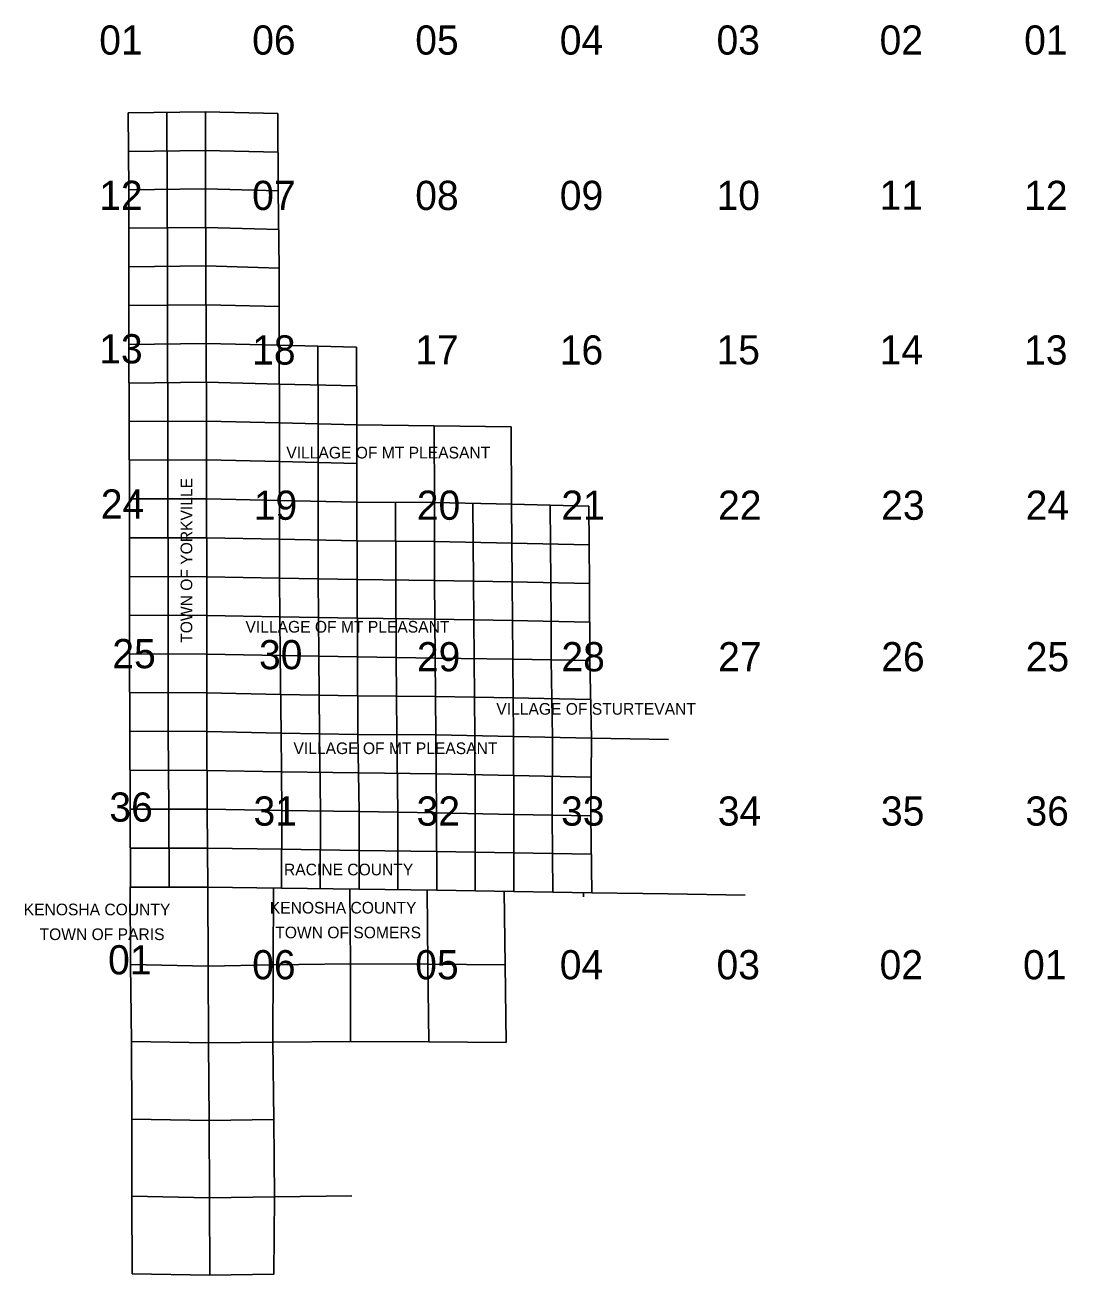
# Model space of a CAD drawing. Extents: x 587895 to 623621, y 151776 to 194601.
import ezdxf

# ---------------------------------------------------------------- set-up
doc = ezdxf.new("R2010")
doc.units = 0
for name, color, linetype in [('E_ALI', 7, 'Continuous'), ('E_ALI_CPI', 7, 'Continuous'), ('E_ALI_Equation', 7, 'Continuous'), ('E_ALI_Sta', 7, 'Continuous')]:
    doc.layers.add(name, color=color, linetype=linetype)

msp = doc.modelspace()

# ---------------------------------------------------------------- linework, layer by layer
at = {"layer": 'E_ALI'}
for p, q in [((591430, 191595), (594075, 191625)), ((594081, 188985), (594075, 191625)), ((594075, 191625), (596550, 191569)), ((594081, 188985), (594091, 186347)), ((591452, 186321), (594091, 186347)), ((594091, 186347), (594100, 183686)), ((594091, 186347), (596599, 186276)), ((594100, 183686), (594107, 181033)), ((599250, 183567), (599256, 180908)), ((594107, 181033), (591459, 181013)), ((594107, 181033), (594113, 178369)), ((596609, 180972), (594107, 181033)), ((599256, 180908), (596609, 180972)), ((599256, 180908), (599265, 178254)), ((599256, 180908), (601913, 180868)), ((601913, 180868), (604543, 180829)), ((604563, 178181), (604543, 180829)), ((594113, 178369), (594118, 175696)), ((599265, 178254), (599268, 175602)), ((604582, 175527), (604563, 178181)), ((591479, 175702), (594118, 175696)), ((594118, 175696), (594121, 173044)), ((594118, 175696), (596616, 175650)), ((596616, 175650), (599268, 175602)), ((599268, 175602), (599282, 172950)), ((599268, 175602), (601923, 175567)), ((601923, 175567), (604582, 175527)), ((604606, 172875), (604582, 175527)), ((604582, 175527), (607227, 175467)), ((594121, 173044), (594127, 170399)), ((599282, 172950), (599296, 170298)), ((604629, 170230), (604606, 172875)), ((591482, 170411), (594127, 170399)), ((594127, 170399), (594140, 167731)), ((594127, 170399), (596664, 170342)), ((596664, 170342), (599296, 170298)), ((599296, 170298), (599341, 167652)), ((599296, 170298), (601971, 170278)), ((601971, 170278), (604629, 170230)), ((604634, 167558), (604629, 170230)), ((604629, 170230), (607296, 170165)), ((607296, 170165), (609932, 170123)), ((594140, 167731), (594155, 165067)), ((599341, 167652), (599341, 164996)), ((604638, 164918), (604634, 167558)), ((591509, 165066), (594155, 165067)), ((594155, 165067), (596682, 165030)), ((594155, 165067), (594166, 162359)), ((596682, 165030), (599341, 164996)), ((599018, 165000), (599030, 163717)), ((599341, 164996), (601999, 164961)), ((601999, 164961), (604638, 164918)), ((604344, 162398), (604307, 164924)), ((604638, 164918), (607310, 164873)), ((607310, 164873), (609922, 164836)), ((609922, 164836), (612561, 164789)), ((599030, 163717), (599041, 162434)), ((594166, 162359), (594182, 159728)), ((599041, 162434), (599050, 159776)), ((604344, 162398), (604378, 159745)), ((591540, 159773), (594182, 159728)), ((594182, 159728), (596389, 159755)), ((596389, 159755), (599050, 159776)), ((599050, 159776), (601722, 159764)), ((601722, 159764), (604378, 159745)), ((594182, 159728), (594199, 157074)), ((594199, 157074), (594209, 154424)), ((591556, 154474), (594209, 154424)), ((594209, 154424), (596440, 154452)), ((594209, 154424), (594227, 151776)), ((596440, 154452), (599095, 154484))]:
    msp.add_line(p, q, dxfattribs=at)
at = {"layer": 'E_ALI_Equation'}
for p, q in [((591430, 191595), (591446, 188952)), ((596550, 191569), (596568, 188923)), ((594081, 188985), (591446, 188952)), ((591446, 188952), (591452, 186321)), ((594081, 188985), (596568, 188923)), ((596568, 188923), (596599, 186276)), ((591452, 186321), (591456, 183659)), ((596599, 186276), (596604, 183628)), ((591456, 183659), (594100, 183686)), ((591456, 183659), (591459, 181013)), ((594100, 183686), (596604, 183628)), ((596604, 183628), (596609, 180972)), ((596604, 183628), (599250, 183567)), ((591459, 181013), (591473, 178363)), ((596609, 180972), (596612, 178313)), ((601916, 178237), (601913, 180868)), ((591473, 178363), (594113, 178369)), ((591473, 178363), (591479, 175702)), ((594113, 178369), (596612, 178313)), ((596612, 178313), (596616, 175650)), ((596612, 178313), (599265, 178254)), ((599265, 178254), (601916, 178237)), ((601923, 175567), (601916, 178237)), ((601916, 178237), (604563, 178181)), ((604563, 178181), (607213, 178117)), ((607213, 178117), (607227, 175467)), ((591479, 175702), (591480, 173056)), ((596616, 175650), (596640, 172998)), ((601947, 172913), (601923, 175567)), ((607227, 175467), (607241, 172825)), ((591480, 173056), (591482, 170411)), ((594121, 173044), (591480, 173056)), ((596640, 172998), (594121, 173044)), ((596640, 172998), (596664, 170342)), ((599282, 172950), (596640, 172998)), ((601947, 172913), (599282, 172950)), ((601971, 170278), (601947, 172913)), ((604606, 172875), (601947, 172913)), ((607241, 172825), (604606, 172875)), ((607241, 172825), (607296, 170165)), ((591482, 170411), (591499, 167739)), ((596664, 170342), (596692, 167690)), ((601985, 167605), (601971, 170278)), ((607296, 170165), (607276, 167509)), ((591499, 167739), (591509, 165066)), ((591499, 167739), (594140, 167731)), ((594140, 167731), (596692, 167690)), ((596692, 167690), (596682, 165030)), ((596692, 167690), (599341, 167652)), ((599341, 167652), (601985, 167605)), ((601999, 164961), (601985, 167605)), ((601985, 167605), (604634, 167558)), ((604634, 167558), (607276, 167509)), ((607276, 167509), (607310, 164873)), ((591492, 165066), (591512, 162418)), ((596405, 165034), (596397, 162401)), ((601696, 162428), (601672, 164965)), ((607023, 164737), (607025, 164877)), ((591512, 162418), (591540, 159773)), ((591512, 162418), (594166, 162359)), ((594166, 162359), (596397, 162401)), ((596397, 162401), (596389, 159755)), ((596397, 162401), (599041, 162434)), ((599041, 162434), (601696, 162428)), ((601722, 159764), (601696, 162428)), ((601696, 162428), (604344, 162398)), ((591540, 159773), (591550, 157118)), ((596389, 159755), (596416, 157103)), ((591550, 157118), (591556, 154474)), ((591550, 157118), (594199, 157074)), ((594199, 157074), (596416, 157103)), ((596416, 157103), (596440, 154452)), ((591556, 154474), (591565, 151819)), ((596440, 154452), (596414, 151805)), ((591565, 151819), (594227, 151776)), ((594227, 151776), (596414, 151805))]:
    msp.add_line(p, q, dxfattribs=at)
at = {"layer": 'E_ALI_Sta'}
for p, q in [((592752, 191610), (592763, 188969)), ((591438, 190273), (594078, 190305)), ((594078, 190305), (596559, 190246)), ((592763, 188969), (592771, 186334)), ((594086, 187666), (591449, 187637)), ((596584, 187600), (594086, 187666)), ((592771, 186334), (592778, 183672)), ((591454, 184990), (594095, 185017)), ((594095, 185017), (596602, 184952)), ((592778, 183672), (592783, 181023)), ((597933, 180940), (597927, 183597)), ((594104, 182360), (591457, 182336)), ((596607, 182300), (594104, 182360)), ((599253, 182237), (596607, 182300)), ((592783, 181023), (592793, 178366)), ((597938, 178283), (597933, 180940)), ((591466, 179688), (594110, 179701)), ((594110, 179701), (596611, 179643)), ((596611, 179643), (599260, 179581)), ((592793, 178366), (592798, 175699)), ((597942, 175626), (597938, 178283)), ((600590, 178245), (600595, 175585)), ((603252, 175547), (603239, 178209)), ((605888, 178149), (605905, 175497)), ((594115, 177032), (591476, 177033)), ((596614, 176982), (594115, 177032)), ((599266, 176928), (596614, 176982)), ((601919, 176902), (599266, 176928)), ((604572, 176854), (601919, 176902)), ((607220, 176792), (604572, 176854)), ((592798, 175699), (592801, 173050)), ((597961, 172974), (597942, 175626)), ((600595, 175585), (600614, 172931)), ((603277, 172894), (603252, 175547)), ((605905, 175497), (605914, 174174)), ((591480, 174379), (594119, 174370)), ((594119, 174370), (596628, 174324)), ((596628, 174324), (599275, 174276)), ((599275, 174276), (601935, 174240)), ((601935, 174240), (604594, 174201)), ((604594, 174201), (607234, 174146)), ((605914, 174174), (605923, 172850)), ((592801, 173050), (592804, 170405)), ((597980, 170320), (597961, 172974)), ((600614, 172931), (600633, 170288)), ((603300, 170254), (603277, 172894)), ((605923, 172850), (605962, 170197)), ((594124, 171722), (591481, 171734)), ((596652, 171670), (594124, 171722)), ((599289, 171624), (596652, 171670)), ((601959, 171595), (599289, 171624)), ((601959, 171595), (604618, 171553)), ((604618, 171553), (607268, 171495)), ((592804, 170405), (592820, 167735)), ((598017, 167671), (597980, 170320)), ((600633, 170288), (600663, 167628)), ((603309, 167581), (603300, 170254)), ((605962, 170197), (605955, 167534)), ((591490, 169075), (594134, 169065)), ((594134, 169065), (596678, 169016)), ((596678, 169016), (599318, 168975)), ((599318, 168975), (601978, 168941)), ((601978, 168941), (604631, 168894)), ((604631, 168894), (607286, 168837)), ((592820, 167735), (592832, 165067)), ((598011, 165013), (598017, 167671)), ((600663, 167628), (600670, 164978)), ((603319, 164940), (603309, 167581)), ((605955, 167534), (605974, 164895)), ((594148, 166399), (591504, 166403)), ((596687, 166360), (594148, 166399)), ((599341, 166324), (596687, 166360)), ((601992, 166283), (599341, 166324)), ((604636, 166238), (601992, 166283)), ((607293, 166191), (604636, 166238))]:
    msp.add_line(p, q, dxfattribs=at)

# ---------------------------------------------------------------- texts
msp.add_text('Corner Missing', height=12).set_placement((606846, 164848))
at = {"layer": 'E_ALI_CPI'}
for s, height, p in [('01', 1000, (590438, 193587)), ('06', 1000, (595676, 193587)), ('05', 1000, (601262, 193587)), ('04', 1000, (606213, 193587)), ('03', 1000, (611582, 193587)), ('02', 1000, (617167, 193587)), ('01', 1000, (622118, 193587)), ('12', 1000, (590438, 188264)), ('07', 1000, (595676, 188264)), ('08', 1000, (601262, 188264)), ('09', 1000, (606213, 188264)), ('10', 1000, (611582, 188264)), ('11', 1000, (617167, 188271)), ('12', 1000, (622118, 188264)), ('13', 1000, (590438, 183009)), ('18', 1000, (595676, 182968)), ('17', 1000, (601262, 182975)), ('16', 1000, (606213, 182969)), ('15', 1000, (611582, 182975)), ('14', 1000, (617167, 182975)), ('13', 1000, (622118, 182968)), ('VILLAGE OF MT PLEASANT', 400, (596846, 179751)), ('24', 1000, (590492, 177690)), ('19', 1000, (595731, 177650)), ('20', 1000, (601317, 177650)), ('21', 1000, (606267, 177650)), ('22', 1000, (611636, 177650)), ('23', 1000, (617222, 177650)), ('24', 1000, (622172, 177650)), ('VILLAGE OF MT PLEASANT', 400, (595447, 173785)), ('25', 1000, (590885, 172565)), ('30', 1000, (595911, 172529)), ('29', 1000, (601319, 172459)), ('28', 1000, (606269, 172459)), ('27', 1000, (611638, 172459)), ('26', 1000, (617224, 172459)), ('25', 1000, (622174, 172459)), ('VILLAGE OF STURTEVANT', 400, (604039, 170972)), ('VILLAGE OF MT PLEASANT', 400, (597091, 169622)), ('36', 1000, (590785, 167309)), ('31', 1000, (595723, 167172)), ('32', 1000, (601309, 167172)), ('33', 1000, (606259, 167172)), ('34', 1000, (611628, 167172)), ('35', 1000, (617214, 167172)), ('36', 1000, (622164, 167172)), ('RACINE COUNTY', 400, (596766, 165468)), ('KENOSHA COUNTY', 400, (587851, 164099)), ('KENOSHA COUNTY', 400, (596280, 164160)), ('TOWN OF PARIS', 400, (588394, 163251)), ('TOWN OF SOMERS', 400, (596468, 163311)), ('01', 1000, (590741, 162076)), ('06', 1000, (595676, 161907)), ('05', 1000, (601262, 161907)), ('04', 1000, (606213, 161907)), ('03', 1000, (611582, 161907)), ('02', 1000, (617167, 161907)), ('01', 1000, (622082, 161907))]:
    msp.add_text(s, height=height, dxfattribs=at).set_placement(p)
msp.add_text('TOWN OF YORKVILLE', height=400, rotation=90, dxfattribs=at).set_placement((593625, 173436))

doc.saveas('drawing.dxf')
